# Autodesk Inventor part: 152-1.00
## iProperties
Created: 2007-06
Part Number: 152-1.00
Document SubType Name: Modeling
Designer: btaylor
Density: 1 g/cm^3
Author: btaylor
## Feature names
1. Sweep1
2. Extrusion1
3. Extrusion2
4. Fillet1
5. Fillet2
6. Extrusion3
7. Chamfer1
8. Fillet3
9. Sweep2
10. Fillet4
11. Chamfer2
12. Fillet5
13. Fillet6
